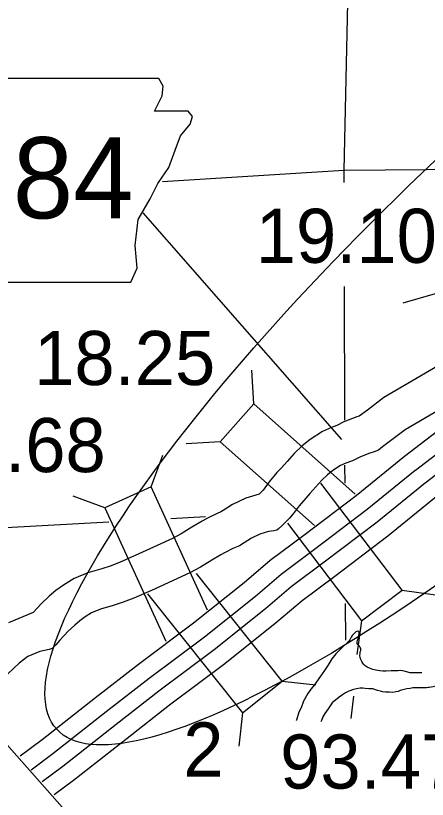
# Model space of a CAD drawing. Extents: x 22866 to 28196, y 1324810 to 1328105.
# Drawn here: x 24094.2 to 24201, y 1326894.3 to 1327097.7 of the extents above; entities that cross this region are included whole.
import ezdxf

# ---------------------------------------------------------------- set-up
doc = ezdxf.new("R2010")
doc.units = 0
for name, color, linetype in [('Default', 7, 'Continuous'), ('Level 10', 7, 'Continuous'), ('Level 19', 7, 'Continuous'), ('Level 20', 7, 'Continuous'), ('Level 21', 7, 'Continuous'), ('Level 4', 7, 'Continuous'), ('Level 5', 7, 'Continuous'), ('Level 58', 7, 'Continuous'), ('Level 9', 7, 'Continuous')]:
    doc.layers.add(name, color=color, linetype=linetype)

msp = doc.modelspace()

# ---------------------------------------------------------------- linework, layer by layer
at = {"layer": 'Default'}
msp.add_ellipse((24246.97, 1327041), major_axis=(-142.09, -128.47), ratio=0.229165, dxfattribs=at)
at = {"layer": 'Level 10'}
for points in [[(24209.88, 1327010.37), (24189.78, 1326998.58)], [(24209.88, 1327010.37), (24189.78, 1326998.58)], [(24215.79, 1327002.27), (24195.31, 1326990.26)], [(24215.79, 1327002.27), (24195.31, 1326990.26)], [(24189.78, 1326998.58), (24185.49, 1326995.36), (24183.37, 1326993.76), (24182.71, 1326993.57), (24179.42, 1326992.29), (24177.53, 1326991.33), (24176.17, 1326990.8), (24173.81, 1326989.81), (24170.62, 1326987.73), (24168.55, 1326986.04), (24166.46, 1326984.1), (24164.64, 1326982.01), (24163.19, 1326980.38), (24162.03, 1326979.12), (24159.99, 1326976.71), (24158.43, 1326974.59), (24158.04, 1326974.14), (24157.38, 1326973.5), (24153.97, 1326972.5), (24150.52, 1326970.82), (24148.09, 1326969.27), (24147.68, 1326969), (24146.34, 1326968.44), (24144.04, 1326967.27), (24142.64, 1326966.55), (24139.96, 1326964.98), (24137.19, 1326963.26), (24134.96, 1326962.07), (24130.92, 1326960.18), (24126.2, 1326958.02), (24121.13, 1326955.79), (24118.75, 1326954.88), (24116.57, 1326954.16), (24112.96, 1326953.08), (24109.38, 1326951.64), (24106.66, 1326949.95), (24104.69, 1326948.49), (24102.96, 1326947.02), (24100.83, 1326945.04), (24098.79, 1326942.85), (24092.33, 1326940.12)], [(24189.78, 1326998.58), (24185.49, 1326995.36), (24183.37, 1326993.76), (24182.71, 1326993.57), (24179.42, 1326992.29), (24177.53, 1326991.33), (24176.17, 1326990.8), (24173.81, 1326989.81), (24170.62, 1326987.73), (24168.55, 1326986.04), (24166.46, 1326984.1), (24164.64, 1326982.01), (24163.19, 1326980.38), (24162.03, 1326979.12), (24159.99, 1326976.71), (24158.43, 1326974.59), (24158.04, 1326974.14), (24157.38, 1326973.5), (24153.97, 1326972.5), (24150.52, 1326970.82), (24148.09, 1326969.27), (24147.68, 1326969), (24146.34, 1326968.44), (24144.04, 1326967.27), (24142.64, 1326966.55), (24139.96, 1326964.98), (24137.19, 1326963.26), (24134.96, 1326962.07), (24130.92, 1326960.18), (24126.2, 1326958.02), (24121.13, 1326955.79), (24118.75, 1326954.88), (24116.57, 1326954.16), (24112.96, 1326953.08), (24109.38, 1326951.64), (24106.66, 1326949.95), (24104.69, 1326948.49), (24102.96, 1326947.02), (24100.83, 1326945.04), (24098.79, 1326942.85), (24092.33, 1326940.12)], [(24195.31, 1326990.26), (24191.49, 1326987.39), (24189.4, 1326985.81), (24188.41, 1326984.96), (24187.27, 1326984.5), (24185.88, 1326984.1), (24183.51, 1326983.18), (24181.61, 1326982.21), (24179.89, 1326981.55), (24178.51, 1326980.97), (24176.52, 1326979.67), (24175.1, 1326978.51), (24173.63, 1326977.15), (24172.13, 1326975.43), (24170.58, 1326973.69), (24169.51, 1326972.52), (24167.82, 1326970.53), (24166.26, 1326968.39), (24165.31, 1326967.29), (24163.38, 1326965.43), (24162.3, 1326964.45), (24162.01, 1326964.2), (24161.25, 1326964.04), (24159.83, 1326963.82), (24157.58, 1326963.16), (24155.4, 1326962.1), (24153.48, 1326960.88), (24152.34, 1326960.14), (24150.54, 1326959.39), (24148.59, 1326958.39), (24147.43, 1326957.8), (24145.11, 1326956.44), (24142.18, 1326954.62), (24139.42, 1326953.15), (24135.11, 1326951.13), (24130.29, 1326948.92), (24124.92, 1326946.56), (24122.1, 1326945.48), (24119.57, 1326944.64), (24116.25, 1326943.66), (24113.91, 1326942.71), (24112.27, 1326941.69), (24110.9, 1326940.68), (24109.6, 1326939.57), (24107.87, 1326937.97), (24105.72, 1326935.66), (24104.66, 1326934.44), (24104.35, 1326934.1), (24103.81, 1326933.57), (24103.78, 1326933.55), (24103.71, 1326933.51), (24103.16, 1326933.3), (24102.91, 1326933.22), (24100.47, 1326932.73), (24097.38, 1326931.43), (24095.13, 1326929.7), (24092.16, 1326926.92)], [(24195.31, 1326990.26), (24191.49, 1326987.39), (24189.4, 1326985.81), (24188.41, 1326984.96), (24187.27, 1326984.5), (24185.88, 1326984.1), (24183.51, 1326983.18), (24181.61, 1326982.21), (24179.89, 1326981.55), (24178.51, 1326980.97), (24176.52, 1326979.67), (24175.1, 1326978.51), (24173.63, 1326977.15), (24172.13, 1326975.43), (24170.58, 1326973.69), (24169.51, 1326972.52), (24167.82, 1326970.53), (24166.26, 1326968.39), (24165.31, 1326967.29), (24163.38, 1326965.43), (24162.3, 1326964.45), (24162.01, 1326964.2), (24161.25, 1326964.04), (24159.83, 1326963.82), (24157.58, 1326963.16), (24155.4, 1326962.1), (24153.48, 1326960.88), (24152.34, 1326960.14), (24150.54, 1326959.39), (24148.59, 1326958.39), (24147.43, 1326957.8), (24145.11, 1326956.44), (24142.18, 1326954.62), (24139.42, 1326953.15), (24135.11, 1326951.13), (24130.29, 1326948.92), (24124.92, 1326946.56), (24122.1, 1326945.48), (24119.57, 1326944.64), (24116.25, 1326943.66), (24113.91, 1326942.71), (24112.27, 1326941.69), (24110.9, 1326940.68), (24109.6, 1326939.57), (24107.87, 1326937.97), (24105.72, 1326935.66), (24104.66, 1326934.44), (24104.35, 1326934.1), (24103.81, 1326933.57), (24103.78, 1326933.55), (24103.71, 1326933.51), (24103.16, 1326933.3), (24102.91, 1326933.22), (24100.47, 1326932.73), (24097.38, 1326931.43), (24095.13, 1326929.7), (24092.16, 1326926.92)]]:
    msp.add_lwpolyline(points, dxfattribs=at)
at = {"layer": 'Level 19'}
for points in [[(24233.89, 1327012.98), (24195.1, 1326983.27)], [(24233.89, 1327012.98), (24195.1, 1326983.27)], [(24236.78, 1327009.44), (24197.95, 1326979.7)], [(24236.78, 1327009.44), (24197.95, 1326979.7)], [(24239.41, 1327006.22), (24200.48, 1326976.4)], [(24239.41, 1327006.22), (24200.48, 1326976.4)], [(24195.1, 1326983.27), (24182.61, 1326973.12), (24169.02, 1326962.83), (24160.26, 1326956.28), (24153.52, 1326950.53), (24140.39, 1326940.06), (24126.1, 1326929.34), (24114.93, 1326920.64), (24101.12, 1326909.79), (24095.44, 1326905.5)], [(24195.1, 1326983.27), (24182.61, 1326973.12), (24169.02, 1326962.83), (24160.26, 1326956.28), (24153.52, 1326950.53), (24140.39, 1326940.06), (24126.1, 1326929.34), (24114.93, 1326920.64), (24101.12, 1326909.79), (24095.44, 1326905.5)], [(24197.91, 1326979.66), (24185.43, 1326969.52), (24171.77, 1326959.18), (24163.11, 1326952.71), (24156.43, 1326947), (24143.19, 1326936.44), (24128.88, 1326925.7), (24117.75, 1326917.04), (24103.91, 1326906.17), (24098.24, 1326901.89)], [(24197.91, 1326979.66), (24185.43, 1326969.52), (24171.77, 1326959.18), (24163.11, 1326952.71), (24156.43, 1326947), (24143.19, 1326936.44), (24128.88, 1326925.7), (24117.75, 1326917.04), (24103.91, 1326906.17), (24098.24, 1326901.89)], [(24200.53, 1326976.44), (24187.99, 1326966.25), (24174.27, 1326955.86), (24165.71, 1326949.46), (24159.07, 1326943.8), (24145.73, 1326933.15), (24131.4, 1326922.4), (24120.31, 1326913.76), (24106.44, 1326902.88), (24101.1, 1326898.84)], [(24200.53, 1326976.44), (24187.99, 1326966.25), (24174.27, 1326955.86), (24165.71, 1326949.46), (24159.07, 1326943.8), (24145.73, 1326933.15), (24131.4, 1326922.4), (24120.31, 1326913.76), (24106.44, 1326902.88), (24101.1, 1326898.84)], [(24203.34, 1326972.83), (24190.82, 1326962.66), (24177.02, 1326952.2), (24168.56, 1326945.88), (24161.98, 1326940.27), (24148.53, 1326929.54), (24134.18, 1326918.77), (24123.12, 1326910.16), (24109.23, 1326899.26), (24104.23, 1326895.48)], [(24203.34, 1326972.83), (24190.82, 1326962.66), (24177.02, 1326952.2), (24168.56, 1326945.88), (24161.98, 1326940.27), (24148.53, 1326929.54), (24134.18, 1326918.77), (24123.12, 1326910.16), (24109.23, 1326899.26), (24104.23, 1326895.48)]]:
    msp.add_lwpolyline(points, dxfattribs=at)
at = {"layer": 'Level 20'}
for p, q in [((24203.1, 1327025.51), (24194.65, 1327023.12)), ((24203.1, 1327025.51), (24194.65, 1327023.12)), ((24156.02, 1326996.96), (24155.51, 1327005.72)), ((24156.02, 1326996.96), (24155.51, 1327005.72)), ((24156.02, 1326996.96), (24147.27, 1326987.12)), ((24156.02, 1326996.96), (24147.27, 1326987.12)), ((24182.34, 1326973.55), (24156.02, 1326996.96)), ((24182.34, 1326973.55), (24156.02, 1326996.96)), ((24147.27, 1326987.12), (24138.51, 1326986.61)), ((24147.27, 1326987.12), (24138.51, 1326986.61)), ((24147.27, 1326987.12), (24171.73, 1326965.36)), ((24147.27, 1326987.12), (24171.73, 1326965.36)), ((24129.36, 1326975.47), (24132.42, 1326983.69)), ((24129.36, 1326975.47), (24132.42, 1326983.69)), ((24194.47, 1326948.61), (24173.39, 1326976.43)), ((24194.47, 1326948.61), (24173.39, 1326976.43)), ((24129.36, 1326975.47), (24117.38, 1326969.99)), ((24129.36, 1326975.47), (24117.38, 1326969.99)), ((24144, 1326943.47), (24129.36, 1326975.47)), ((24144, 1326943.47), (24129.36, 1326975.47)), ((24117.38, 1326969.99), (24109.16, 1326973.05)), ((24117.38, 1326969.99), (24109.16, 1326973.05)), ((24117.38, 1326969.99), (24133.21, 1326935.41)), ((24117.38, 1326969.99), (24133.21, 1326935.41)), ((24164.74, 1326966.05), (24183.97, 1326940.65)), ((24164.74, 1326966.05), (24183.97, 1326940.65)), ((24163.39, 1326925.02), (24141.14, 1326952.92)), ((24163.39, 1326925.02), (24141.14, 1326952.92)), ((24128.47, 1326947.69), (24153.1, 1326916.81)), ((24128.47, 1326947.69), (24153.1, 1326916.81)), ((24183.97, 1326940.65), (24194.47, 1326948.61)), ((24183.97, 1326940.65), (24194.47, 1326948.61)), ((24194.47, 1326948.61), (24203.16, 1326947.41)), ((24194.47, 1326948.61), (24203.16, 1326947.41)), ((24183.97, 1326940.65), (24182.78, 1326931.96)), ((24183.97, 1326940.65), (24182.78, 1326931.96)), ((24153.1, 1326916.81), (24163.39, 1326925.02)), ((24153.1, 1326916.81), (24163.39, 1326925.02)), ((24163.39, 1326925.02), (24172.11, 1326924.04)), ((24163.39, 1326925.02), (24172.11, 1326924.04)), ((24153.1, 1326916.81), (24152.12, 1326908.09)), ((24153.1, 1326916.81), (24152.12, 1326908.09))]:
    msp.add_line(p, q, dxfattribs=at)
msp.add_lwpolyline([(24076.08, 1326906.49), (24102.29, 1326876.94), (24112.14, 1326885.67), (24085.94, 1326915.23)], close=True, dxfattribs=at)
msp.add_lwpolyline([(24076.08, 1326906.49), (24102.29, 1326876.94), (24112.14, 1326885.67), (24085.94, 1326915.23)], close=True, dxfattribs=at)
at = {"layer": 'Level 21'}
msp.add_line((24127.19, 1327046.51), (24178.81, 1326987.75), dxfattribs=at)
msp.add_line((24127.19, 1327046.51), (24178.81, 1326987.75), dxfattribs=at)
msp.add_lwpolyline([(24080.77, 1327081.41), (24083.3, 1327064.53), (24082.18, 1327038.94), (24084.43, 1327037.53), (24088.65, 1327037.53), (24088.65, 1327028.53), (24124.09, 1327028.53), (24125.77, 1327032.19), (24125.21, 1327038.1), (24126.05, 1327044.85), (24129.15, 1327050.19), (24131.12, 1327054.13), (24133.93, 1327058.35), (24135.62, 1327062.85), (24137.02, 1327066.5), (24139.55, 1327069.6), (24140.12, 1327071.57), (24138.99, 1327072.97), (24130.27, 1327072.97), (24132.24, 1327076.91), (24132.52, 1327079.44), (24131.36, 1327081.38)], close=True, dxfattribs=at)
msp.add_lwpolyline([(24080.77, 1327081.41), (24083.3, 1327064.53), (24082.18, 1327038.94), (24084.43, 1327037.53), (24088.65, 1327037.53), (24088.65, 1327028.53), (24124.09, 1327028.53), (24125.77, 1327032.19), (24125.21, 1327038.1), (24126.05, 1327044.85), (24129.15, 1327050.19), (24131.12, 1327054.13), (24133.93, 1327058.35), (24135.62, 1327062.85), (24137.02, 1327066.5), (24139.55, 1327069.6), (24140.12, 1327071.57), (24138.99, 1327072.97), (24130.27, 1327072.97), (24132.24, 1327076.91), (24132.52, 1327079.44), (24131.36, 1327081.38)], close=True, dxfattribs=at)
at = {"layer": 'Level 4'}
for points in [[(24181.3, 1327144.57), (24179.34, 1327057.63), (24179.35, 1327054.44)], [(24181.3, 1327144.57), (24179.34, 1327057.63), (24179.35, 1327054.44)], [(24179.44, 1327027.39), (24179.55, 1326992.71)], [(24179.44, 1327027.39), (24179.55, 1326992.71)], [(24179.59, 1326981.02), (24179.6, 1326976.35)], [(24179.59, 1326981.02), (24179.6, 1326976.35)], [(24179.73, 1326945.18), (24179.77, 1326935.6)], [(24179.73, 1326945.18), (24179.77, 1326935.6)], [(24181.85, 1326921.1), (24181.22, 1326915.28)], [(24181.85, 1326921.1), (24181.22, 1326915.28)]]:
    msp.add_lwpolyline(points, dxfattribs=at)
at = {"layer": 'Level 5'}
for points in [[(24132.35, 1327054.69), (24179.34, 1327057.63), (24254.72, 1327058.24)], [(24132.35, 1327054.69), (24179.34, 1327057.63), (24254.72, 1327058.24)], [(24118.44, 1326966.27), (24091.64, 1326964.78), (24013.43, 1326965.78)], [(24118.44, 1326966.27), (24091.64, 1326964.78), (24013.43, 1326965.78)], [(24143.5, 1326967.67), (24134.52, 1326967.17)], [(24143.5, 1326967.67), (24134.52, 1326967.17)]]:
    msp.add_lwpolyline(points, dxfattribs=at)
at = {"layer": 'Level 9'}
for points in [[(24199.65, 1326927.2), (24198.07, 1326927.16), (24196.57, 1326927.18), (24195.04, 1326927.57), (24194.14, 1326927.73), (24193.51, 1326927.69), (24192.92, 1326927.72), (24191.69, 1326927.68), (24190.33, 1326927.56), (24189.53, 1326927.62), (24188.73, 1326927.68), (24188.24, 1326927.78), (24187.7, 1326927.87), (24186.91, 1326928.07), (24186.01, 1326928.36), (24185.47, 1326928.62), (24184.91, 1326929.02), (24184.54, 1326929.35), (24184.3, 1326929.68), (24184.03, 1326930.14), (24183.76, 1326930.64), (24183.59, 1326931.14), (24183.52, 1326931.63), (24183.59, 1326932.2), (24183.65, 1326932.6), (24183.78, 1326933), (24183.78, 1326933.07), (24183.77, 1326933.5), (24183.64, 1326933.73), (24183.4, 1326934.1), (24183, 1326934.53), (24182.87, 1326934.79), (24182.83, 1326935.09), (24182.89, 1326935.62), (24183.06, 1326935.99), (24183.12, 1326936.23), (24183.12, 1326936.33), (24183.22, 1326936.69), (24183.25, 1326936.86), (24183.31, 1326937.06), (24183.38, 1326937.36), (24183.38, 1326937.49), (24183.37, 1326937.73), (24183.34, 1326937.86), (24183.01, 1326937.96), (24182.51, 1326937.82), (24182.18, 1326937.45), (24181.56, 1326936.81), (24181.29, 1326936.41), (24180.9, 1326935.74), (24180.61, 1326935.24), (24180.34, 1326935), (24179.02, 1326933.79), (24177.31, 1326932.11), (24176.29, 1326930.81), (24175.21, 1326929.1), (24174.33, 1326927.76), (24173.74, 1326926.86), (24172.88, 1326925.65), (24171.93, 1326924.34), (24171.37, 1326923.54), (24170.85, 1326922.9), (24170.03, 1326921.8), (24168.92, 1326919.82), (24168.27, 1326918.12), (24167.71, 1326916.92), (24167.06, 1326914.88), (24167.04, 1326914.76)], [(24199.65, 1326927.2), (24198.07, 1326927.16), (24196.57, 1326927.18), (24195.04, 1326927.57), (24194.14, 1326927.73), (24193.51, 1326927.69), (24192.92, 1326927.72), (24191.69, 1326927.68), (24190.33, 1326927.56), (24189.53, 1326927.62), (24188.73, 1326927.68), (24188.24, 1326927.78), (24187.7, 1326927.87), (24186.91, 1326928.07), (24186.01, 1326928.36), (24185.47, 1326928.62), (24184.91, 1326929.02), (24184.54, 1326929.35), (24184.3, 1326929.68), (24184.03, 1326930.14), (24183.76, 1326930.64), (24183.59, 1326931.14), (24183.52, 1326931.63), (24183.59, 1326932.2), (24183.65, 1326932.6), (24183.78, 1326933), (24183.78, 1326933.07), (24183.77, 1326933.5), (24183.64, 1326933.73), (24183.4, 1326934.1), (24183, 1326934.53), (24182.87, 1326934.79), (24182.83, 1326935.09), (24182.89, 1326935.62), (24183.06, 1326935.99), (24183.12, 1326936.23), (24183.12, 1326936.33), (24183.22, 1326936.69), (24183.25, 1326936.86), (24183.31, 1326937.06), (24183.38, 1326937.36), (24183.38, 1326937.49), (24183.37, 1326937.73), (24183.34, 1326937.86), (24183.01, 1326937.96), (24182.51, 1326937.82), (24182.18, 1326937.45), (24181.56, 1326936.81), (24181.29, 1326936.41), (24180.9, 1326935.74), (24180.61, 1326935.24), (24180.34, 1326935), (24179.02, 1326933.79), (24177.31, 1326932.11), (24176.29, 1326930.81), (24175.21, 1326929.1), (24174.33, 1326927.76), (24173.74, 1326926.86), (24172.88, 1326925.65), (24171.93, 1326924.34), (24171.37, 1326923.54), (24170.85, 1326922.9), (24170.03, 1326921.8), (24168.92, 1326919.82), (24168.27, 1326918.12), (24167.71, 1326916.92), (24167.06, 1326914.88), (24167.04, 1326914.76)], [(24200.82, 1326923.25), (24198.3, 1326923.27), (24197.3, 1326923.3), (24196.61, 1326923.12), (24195.74, 1326923.02), (24195.41, 1326922.95), (24194.65, 1326922.77), (24193.99, 1326922.57), (24193.46, 1326922.36), (24192.86, 1326922.19), (24192.1, 1326922.05), (24191.14, 1326922.11), (24190.17, 1326922.17), (24189.38, 1326922.23), (24188.88, 1326922.42), (24188.15, 1326922.62), (24186.88, 1326922.97), (24185.85, 1326923.03), (24184.89, 1326923.12), (24184.32, 1326923.18), (24183.59, 1326923.14), (24183.1, 1326923.11), (24181.87, 1326922.86), (24180.68, 1326922.39), (24179.85, 1326921.95), (24178.99, 1326921.41), (24178.17, 1326920.87), (24176.39, 1326919.35), (24175.3, 1326917.85), (24174.42, 1326916.57), (24173.96, 1326915.77), (24173.6, 1326914.8), (24173.45, 1326914.43)], [(24200.82, 1326923.25), (24198.3, 1326923.27), (24197.3, 1326923.3), (24196.61, 1326923.12), (24195.74, 1326923.02), (24195.41, 1326922.95), (24194.65, 1326922.77), (24193.99, 1326922.57), (24193.46, 1326922.36), (24192.86, 1326922.19), (24192.1, 1326922.05), (24191.14, 1326922.11), (24190.17, 1326922.17), (24189.38, 1326922.23), (24188.88, 1326922.42), (24188.15, 1326922.62), (24186.88, 1326922.97), (24185.85, 1326923.03), (24184.89, 1326923.12), (24184.32, 1326923.18), (24183.59, 1326923.14), (24183.1, 1326923.11), (24181.87, 1326922.86), (24180.68, 1326922.39), (24179.85, 1326921.95), (24178.99, 1326921.41), (24178.17, 1326920.87), (24176.39, 1326919.35), (24175.3, 1326917.85), (24174.42, 1326916.57), (24173.96, 1326915.77), (24173.6, 1326914.8), (24173.45, 1326914.43)], [(24205.38, 1326923.87), (24204.26, 1326923.81), (24203.4, 1326923.7), (24202.87, 1326923.59), (24202.54, 1326923.55), (24201.55, 1326923.37), (24201.22, 1326923.33), (24200.82, 1326923.25)], [(24205.38, 1326923.87), (24204.26, 1326923.81), (24203.4, 1326923.7), (24202.87, 1326923.59), (24202.54, 1326923.55), (24201.55, 1326923.37), (24201.22, 1326923.33), (24200.82, 1326923.25)]]:
    msp.add_lwpolyline(points, dxfattribs=at)

# ---------------------------------------------------------------- texts
at = {"layer": 'Level 20'}
msp.add_text('2', height=14.04, dxfattribs=at).set_placement((24137.71, 1326900.25))
msp.add_text('2', height=14.04, dxfattribs=at).set_placement((24137.71, 1326900.25))
at = {"layer": 'Level 21'}
msp.add_text('84', height=21.066, dxfattribs=at).set_placement((24093.48, 1327045.12))
msp.add_text('84', height=21.066, dxfattribs=at).set_placement((24093.48, 1327045.12))
at = {"layer": 'Level 58'}
for s, height, p in [('19.10', 14.044, (24156.53, 1327033.57)), ('19.10', 14.044, (24156.53, 1327033.57)), ('18.25', 14.044, (24099.02, 1327001.85)), ('18.25', 14.044, (24099.02, 1327001.85)), ('17.68', 14.044, (24070.61, 1326979.26)), ('17.68', 14.044, (24070.61, 1326979.26)), ('93.47,93.51', 14.0442, (24162.85, 1326897.12)), ('93.47,93.51', 14.0442, (24162.85, 1326897.12))]:
    msp.add_text(s, height=height, dxfattribs=at).set_placement(p)

doc.saveas('drawing.dxf')
